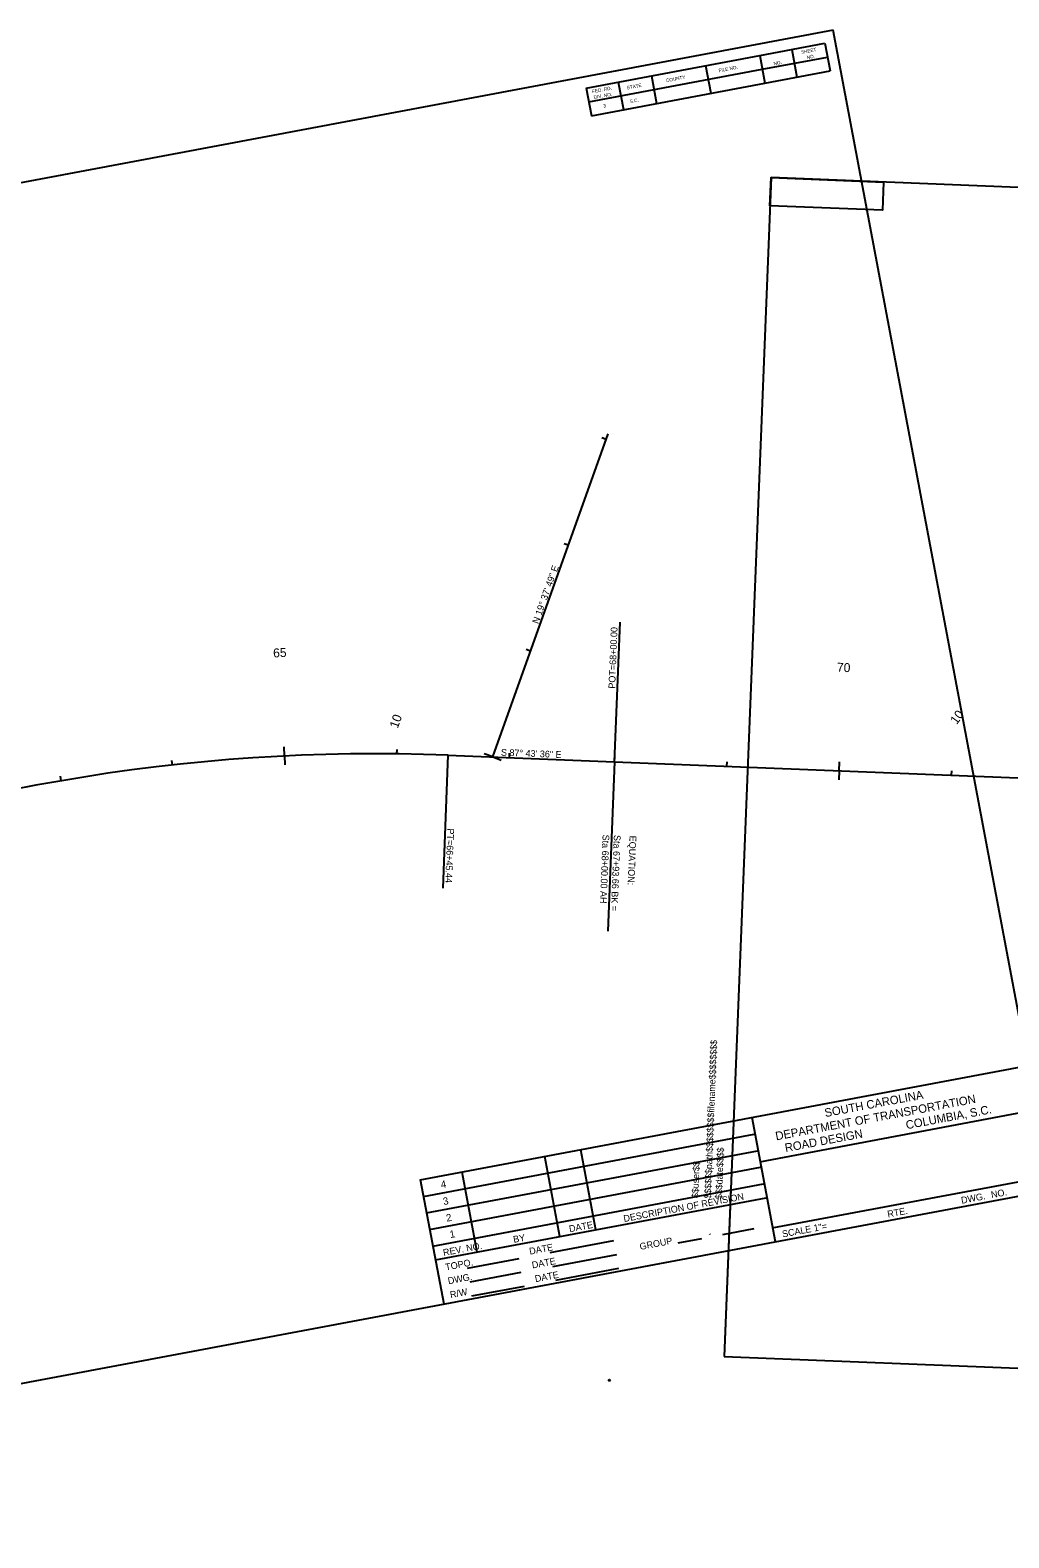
# Model space of a CAD drawing. Extents: x 1965566 to 1970293, y 1116554 to 1118568.
# Drawn here: x 1967960 to 1968830, y 1117226 to 1118568 of the extents above; entities that cross this region are included whole.
import ezdxf

# ---------------------------------------------------------------- set-up
doc = ezdxf.new("R2010")
doc.units = 0
for name, color, linetype in [('Level 1', 7, 'Continuous'), ('Level 21', 7, 'Continuous'), ('Level 35', 7, 'Continuous')]:
    doc.layers.add(name, color=color, linetype=linetype)

msp = doc.modelspace()

# ---------------------------------------------------------------- linework, layer by layer
at = {"layer": 'Level 1'}
for p, q in [((1968674.2, 1118567.8), (1967028.1, 1118258)), ((1968868.4, 1117535.9), (1968674.2, 1118567.8)), ((1968608.8, 1118545.3), (1968666.7, 1118556.2)), ((1968637.3, 1118550.7), (1968641.9, 1118526.1)), ((1968666.7, 1118556.2), (1968671.4, 1118531.6)), ((1968454.5, 1118516.3), (1968608.8, 1118545.3)), ((1968560.6, 1118536.2), (1968565.2, 1118511.7)), ((1968608.8, 1118545.3), (1968613.4, 1118520.7)), ((1968611.1, 1118533), (1968669.1, 1118543.9)), ((1968456.8, 1118504), (1968611.1, 1118533)), ((1968459.1, 1118491.7), (1968613.4, 1118520.7)), ((1968483, 1118521.6), (1968487.6, 1118497.1)), ((1968512.4, 1118527.2), (1968517.1, 1118502.6)), ((1968613.4, 1118520.7), (1968671.4, 1118531.6)), ((1968454.5, 1118516.3), (1968459.1, 1118491.7)), ((1968618.9, 1118436.6), (1968577.2, 1117387.4)), ((1970292.6, 1118370.1), (1968618.9, 1118436.6)), ((1968371.4, 1117921), (1968474, 1118208.6)), ((1968371.4, 1117921), (1968474, 1118208.6)), ((1968472.1, 1118203.5), (1968468.4, 1118204.9)), ((1968438.5, 1118109.4), (1968434.8, 1118110.7)), ((1968479.6, 1117916.7), (1968484.6, 1118040.9)), ((1968404.9, 1118015.2), (1968401.2, 1118016.5)), ((1968086.5, 1117913.9), (1968086, 1117917.9)), ((1968186.2, 1117921.9), (1968185.8, 1117929.9)), ((1968186.2, 1117921.9), (1968186.5, 1117913.9)), ((1968286.1, 1117923.7), (1968286.2, 1117927.7)), ((1968331.5, 1117922.6), (1968326.9, 1117804.4)), ((1968331.5, 1117922.6), (1968479.6, 1117916.7)), ((1968371.4, 1117921), (1968363.8, 1117923.7)), ((1968371.4, 1117921), (1968378.9, 1117918.3)), ((1968386.1, 1117920.4), (1968386.2, 1117924.4)), ((1968479.6, 1117916.7), (1968479.8, 1117920.7)), ((1967987.5, 1117899.9), (1967986.8, 1117903.8)), ((1968479.6, 1117916.7), (1968473.7, 1117765.9)), ((1968479.6, 1117916.7), (1969279, 1117884.9)), ((1968579.6, 1117912.7), (1968579.7, 1117916.7)), ((1968679.5, 1117908.7), (1968679.2, 1117900.8)), ((1968679.5, 1117908.7), (1968679.8, 1117916.7)), ((1968779.4, 1117904.8), (1968779.6, 1117908.8)), ((1968306.9, 1117544.7), (1968847.6, 1117646.5)), ((1968622.8, 1117489.5), (1968602, 1117600.2)), ((1968608.8, 1117560.8), (1968855, 1117607.2)), ((1968309.7, 1117530), (1968603.9, 1117585.3)), ((1968312.5, 1117515.2), (1968606.7, 1117570.6)), ((1968463.1, 1117500.2), (1968449.6, 1117571.5)), ((1968315.2, 1117500.5), (1968609.5, 1117555.9)), ((1968431.1, 1117494.2), (1968417.7, 1117565.5)), ((1968328, 1117434), (1968307.1, 1117544.7)), ((1968357.4, 1117480.3), (1968344, 1117551.6)), ((1968619.9, 1117501.9), (1968866.1, 1117548.2)), ((1967222.3, 1117226.1), (1968868.4, 1117535.9)), ((1968318, 1117485.7), (1968612.3, 1117541.1)), ((1968320.3, 1117473.5), (1968614.6, 1117528.8)), ((1968583.2, 1117537.3), (1968577.2, 1117387.4)), ((1968575.9, 1117496.1), (1968603.8, 1117501.4)), ((1968422.3, 1117479.9), (1968479, 1117490.6)), ((1968536.3, 1117488.7), (1968557.4, 1117492.6)), ((1968348.9, 1117466.1), (1968394.8, 1117474.8)), ((1968424.7, 1117467.7), (1968481.7, 1117478.4)), ((1968351.2, 1117453.8), (1968396.7, 1117462.4)), ((1968427.4, 1117455.4), (1968483.6, 1117466)), ((1968352.7, 1117441.4), (1968399.5, 1117450.2)), ((1968577.2, 1117387.4), (1970250.9, 1117321))]:
    msp.add_line(p, q, dxfattribs=at)
msp.add_lwpolyline([(1968617.9, 1118411.6), (1968618.9, 1118436.6), (1968718.8, 1118432.6), (1968717.9, 1118407.6)], close=True, dxfattribs=at)
msp.add_arc((1968266.6, 1116286.8), 1637, 87.7266, 111.9958, dxfattribs=at)
at = {"layer": 'Level 35'}
msp.add_circle((1968475.1, 1117366.4), 0.607, dxfattribs=at)

# ---------------------------------------------------------------- texts
at = {"layer": 'Level 1'}
for s, height, rotation, p in [('SHEET', 3, 10.6591, (1968645.8, 1118546.7)), ('FILE NO.', 3, 10.6591, (1968572.5, 1118530.3)), ('NO.', 3, 10.6591, (1968621.4, 1118536.5)), ('NO.', 3, 10.6591, (1968650.9, 1118542)), ('COUNTY', 3, 10.6591, (1968525.7, 1118521.5)), ('FED. RD.', 3, 10.6591, (1968460, 1118511.7)), ('DIV. NO.', 3, 10.6591, (1968461.4, 1118506.4)), ('STATE', 3, 10.6591, (1968490.8, 1118515)), ('3', 3, 10.6591, (1968470, 1118498.8)), ('S.C.', 3, 10.6591, (1968493.5, 1118502.8)), ('POT=68+00.00', 6, 87.7266, (1968480.2, 1117981.7)), ('PT=66+45.44', 6, 267.7266, (1968331, 1117857.5)), ('Sta 68+00.00 AH', 6, 267.7266, (1968469.1, 1117852)), ('Sta 67+93.66 BK = ', 6, 267.7266, (1968479.1, 1117851.7)), ('EQUATION:', 6, 267.7266, (1968493.1, 1117851.1)), ('$$$$$$path$$$$$$$$filename$$$$$$$$', 5.88, 87.7266, (1968565.3, 1117527.9)), ('SOUTH CAROLINA', 7.5, 10.6591, (1968667.2, 1117600.5)), ('DEPARTMENT OF TRANSPORTATION', 7.5, 10.6591, (1968623.5, 1117579.8)), ('COLUMBIA, S.C.', 7.5, 10.6591, (1968739.5, 1117589.7)), ('ROAD DESIGN', 7.5, 10.6591, (1968631.9, 1117569.4)), ('$$$date$$$$', 5.88, 87.7266, (1968575.1, 1117527.5)), ('$$user$$', 5.88, 87.7266, (1968554.1, 1117528.4)), ('4', 6.5, 10.6591, (1968325.7, 1117537.1)), ('3', 6.5, 10.6591, (1968327.7, 1117522.2)), ('DESCRIPTION OF REVISION', 6, 10.6591, (1968488.2, 1117507.1)), ('DWG.', 6, 10.6591, (1968788.5, 1117523.4)), ('NO.', 6, 10.6591, (1968815.1, 1117528.4)), ('2', 6.5, 10.6591, (1968330.5, 1117507.4)), ('RTE.', 6, 10.6591, (1968722.9, 1117511.1)), ('DATE', 6, 10.6591, (1968439.8, 1117498)), ('SCALE 1"=', 6, 10.6591, (1968629.3, 1117493.4)), ('REV. NO.', 6, 10.6591, (1968327.7, 1117476.9)), ('1', 6.5, 10.6591, (1968333.6, 1117492.8)), ('BY', 6, 10.6591, (1968390.1, 1117488.6)), ('DATE', 6, 10.6591, (1968404.4, 1117478.1)), ('GROUP', 6, 10.6591, (1968502.6, 1117482.3)), ('-', 6, 10.6591, (1968563.6, 1117493.8)), ('DATE', 6, 10.6591, (1968406.7, 1117465.8)), ('TOPO.', 6, 10.6591, (1968329.7, 1117464)), ('DWG.', 6, 10.6591, (1968332, 1117451.7)), ('DATE', 6, 10.6591, (1968409.4, 1117453.6)), ('R/W', 6, 10.6591, (1968333.9, 1117439.4))]:
    msp.add_text(s, height=height, rotation=rotation, dxfattribs=at).set_placement(p)
at = {"layer": 'Level 21'}
for s, height, rotation, p in [('N 19%%d 37\' 49" E', 6, 70.3698, (1968411.9, 1118039)), ('65', 8, 2.8171, (1968176.2, 1118009.5)), ('70', 8, 357.7266, (1968677.4, 1117996.9)), ('10', 8, 70.3698, (1968286.8, 1117945.9)), ('10', 8, 54.0772, (1968784, 1117949.3)), ('S 87%%d 43\' 36" E', 6, 357.7266, (1968378.5, 1117922.2))]:
    msp.add_text(s, height=height, rotation=rotation, dxfattribs=at).set_placement(p)

doc.saveas('drawing.dxf')
